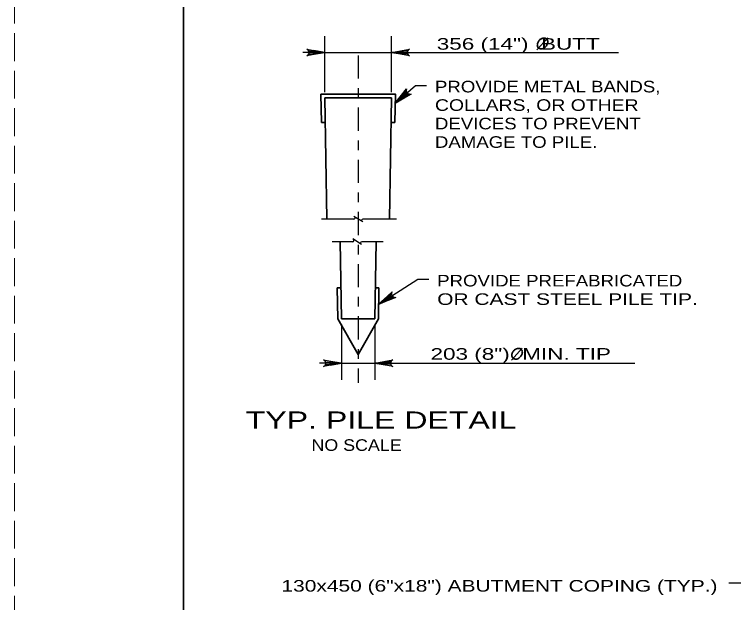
# Model space of a CAD drawing. Extents: x -6.4 to 73.1, y -66 to 0.
# Drawn here: x 0 to 7.44, y -58.43 to -52.34 of the extents above; entities that cross this region are included whole.
import ezdxf
from ezdxf.enums import TextEntityAlignment as Align

# ---------------------------------------------------------------- set-up
doc = ezdxf.new("R2010")
doc.units = 0
doc.header["$LTSCALE"] = 0.048
doc.linetypes.add('DOT_DASHED', pattern=[7.7, 5, -1.2, 0.3, -1.2])
doc.linetypes.add('LONG_DASHED', pattern=[7.5, 6, -1.5])
for name, color, linetype, lineweight in [('1', 7, 'Continuous', 13), ('4', 7, 'Continuous', 25), ('5', 7, 'Continuous', 25), ('63', 7, 'LONG_DASHED', 13)]:
    doc.layers.add(name, color=color, linetype=linetype, lineweight=lineweight)

msp = doc.modelspace()

# ---------------------------------------------------------------- hatches: boundary and pattern name
at = {"layer": '5'}
for points in [[(3.099, -52.71575), (3.099, -52.7535), (3.21242, -52.73458)], [(4.01508, -52.71575), (4.01508, -52.7535), (3.90167, -52.73458)], [(4.03833, -53.20025), (4.01358, -53.17167), (3.94025, -53.26017)], [(3.87675, -55.29392), (3.85625, -55.26217), (3.77117, -55.3395)], [(3.27133, -55.931), (3.27133, -55.96875), (3.38467, -55.94992)], [(3.84275, -55.931), (3.84275, -55.96875), (3.72933, -55.94992)]]:
    msp.add_hatch(color=256, dxfattribs=at).paths.add_polyline_path(points)

# ---------------------------------------------------------------- linework, layer by layer
at = {"layer": '1', "lineweight": 35}
msp.add_lwpolyline([(1.75, -65.25), (33.25, -65.25), (33.25, -44.75), (1.75, -44.75)], close=True, dxfattribs=at)
at = {"layer": '4', "linetype": 'DOT_DASHED'}
msp.add_line((3.557, -52.76425), (3.557, -56.15083), dxfattribs=at)
at = {"layer": '4', "lineweight": 35}
for p, q in [((3.17233, -53.16475), (3.177, -53.46058)), ((3.21242, -53.20417), (3.23217, -54.45908)), ((3.21242, -53.20417), (3.90167, -53.20417)), ((3.90167, -53.20417), (3.88192, -54.45908)), ((3.177, -53.46058), (3.21642, -53.46058)), ((3.89767, -53.46058), (3.93708, -53.46058)), ((3.37208, -54.69267), (3.38467, -55.49142)), ((3.742, -54.69267), (3.72933, -55.49142)), ((3.34142, -55.16983), (3.34533, -55.492)), ((3.34142, -55.16983), (3.38083, -55.16983)), ((3.73325, -55.16983), (3.77258, -55.16983)), ((3.77258, -55.16983), (3.76875, -55.492)), ((3.34533, -55.492), (3.557, -55.85875)), ((3.38467, -55.49142), (3.72933, -55.49142)), ((3.76875, -55.492), (3.557, -55.85875))]:
    msp.add_line(p, q, dxfattribs=at)
at = {"layer": '4'}
for p, q in [((3.51308, -54.45908), (3.17808, -54.45908)), ((3.60533, -54.48808), (3.51292, -54.43)), ((3.95258, -54.45908), (3.60633, -54.45908)), ((3.50067, -54.69267), (3.28917, -54.69267)), ((3.59283, -54.72175), (3.5005, -54.66367)), ((3.81658, -54.69267), (3.59392, -54.69267))]:
    msp.add_line(p, q, dxfattribs=at)
at = {"layer": '4', "lineweight": 35}
msp.add_lwpolyline([(3.17233, -53.16475), (3.94175, -53.16475), (3.93708, -53.46058)], dxfattribs=at)
at = {"layer": '4'}
for centre, start, end in [((3.51185, -54.44546), 275.32859, 57.86724), ((3.60636, -54.47268), 90, 240), ((3.4994, -54.67909), 275.32859, 57.86724), ((3.5939, -54.70631), 90, 240)]:
    msp.add_arc(centre, 0.01364, start, end, dxfattribs=at)
at = {"layer": '5'}
for p, q in [((3.21242, -53.14508), (3.21242, -52.5645)), ((3.90167, -53.14508), (3.90167, -52.5645)), ((3.21242, -52.73458), (2.98558, -52.73458)), ((3.21242, -52.73458), (6.25125, -52.73458)), ((3.90167, -52.73458), (4.1285, -52.73458)), ((3.38467, -55.55042), (3.38467, -56.12)), ((3.72933, -55.55042), (3.72933, -56.12)), ((3.38467, -55.94992), (3.15792, -55.94992)), ((3.38467, -55.94992), (6.42142, -55.94992)), ((3.84275, -55.94992), (3.95617, -55.94992)), ((7.7735, -58.22442), (7.39092, -58.22442))]:
    msp.add_line(p, q, dxfattribs=at)
at = {"layer": '5', "lineweight": 35}
for p, q in [((5.40725, -52.70692), (5.51925, -52.58425)), ((5.14367, -55.91767), (5.25567, -55.79508))]:
    msp.add_line(p, q, dxfattribs=at)
at = {"layer": '5'}
for points in [[(3.21242, -52.73458), (3.026, -52.7695), (3.04033, -52.75958), (3.04775, -52.74708), (3.04992, -52.73458), (3.04775, -52.72208), (3.04033, -52.70958), (3.026, -52.69967), (3.21242, -52.73458), (3.04033, -52.70958), (3.04775, -52.72208), (3.21242, -52.73458), (3.04992, -52.73458), (3.04775, -52.74708), (3.21242, -52.73458), (3.04033, -52.75958)], [(3.90167, -52.73458), (4.08808, -52.69967), (4.07375, -52.70958), (4.06633, -52.72208), (4.06417, -52.73458), (4.06633, -52.74708), (4.07375, -52.75958), (4.08808, -52.7695), (3.90167, -52.73458), (4.07375, -52.75958), (4.06633, -52.74708), (3.90167, -52.73458), (4.06417, -52.73458), (4.06633, -52.72208), (3.90167, -52.73458), (4.07375, -52.70958)], [(3.94025, -53.26017), (4.15083, -53.07783), (4.26425, -53.07783)], [(3.94025, -53.26017), (4.05833, -53.11175), (4.05392, -53.12867), (4.0565, -53.14292), (4.06308, -53.15383), (4.07292, -53.16183), (4.08667, -53.16642), (4.10408, -53.16458), (3.94025, -53.26017), (4.08667, -53.16642), (4.07292, -53.16183), (3.94025, -53.26017), (4.06308, -53.15383), (4.0565, -53.14292), (3.94025, -53.26017), (4.05392, -53.12867)], [(3.77058, -55.33992), (4.17367, -55.08008), (4.28708, -55.08008)], [(3.77058, -55.33992), (3.90833, -55.2095), (3.90167, -55.22567), (3.90217, -55.24017), (3.90717, -55.25183), (3.91575, -55.26125), (3.92875, -55.26775), (3.94617, -55.26833), (3.77058, -55.33992), (3.92875, -55.26775), (3.91575, -55.26125), (3.77058, -55.33992), (3.90717, -55.25183), (3.90217, -55.24017), (3.77058, -55.33992), (3.90167, -55.22567)], [(3.38467, -55.94992), (3.19825, -55.98483), (3.21258, -55.97492), (3.22, -55.96242), (3.22217, -55.94992), (3.22, -55.93742), (3.21258, -55.92492), (3.19825, -55.915), (3.38467, -55.94992), (3.21258, -55.92492), (3.22, -55.93742), (3.38467, -55.94992), (3.22217, -55.94992), (3.22, -55.96242), (3.38467, -55.94992), (3.21258, -55.97492)], [(3.72933, -55.94992), (3.91575, -55.915), (3.90142, -55.92492), (3.894, -55.93742), (3.89183, -55.94992), (3.894, -55.96242), (3.90142, -55.97492), (3.91575, -55.98483), (3.72933, -55.94992), (3.90142, -55.97492), (3.894, -55.96242), (3.72933, -55.94992), (3.89183, -55.94992), (3.894, -55.93742), (3.72933, -55.94992), (3.90142, -55.92492)]]:
    msp.add_lwpolyline(points, dxfattribs=at)
for points in [[(3.099, -52.71575), (3.099, -52.7535), (3.21242, -52.73458)], [(4.01508, -52.71575), (4.01508, -52.7535), (3.90167, -52.73458)], [(4.03833, -53.20025), (4.01358, -53.17167), (3.94025, -53.26017)], [(3.87675, -55.29392), (3.85625, -55.26217), (3.77117, -55.3395)], [(3.27133, -55.931), (3.27133, -55.96875), (3.38467, -55.94992)], [(3.84275, -55.931), (3.84275, -55.96875), (3.72933, -55.94992)]]:
    msp.add_lwpolyline(points, close=True, dxfattribs=at)
at = {"layer": '5', "lineweight": 35}
for points in [[(5.50767, -52.59642), (5.49892, -52.5895), (5.49017, -52.58717), (5.47917, -52.58617), (5.47292, -52.58617), (5.46217, -52.58867), (5.45225, -52.59317), (5.44542, -52.597), (5.43217, -52.60767), (5.42175, -52.62117), (5.4155, -52.63375), (5.41192, -52.64542), (5.41075, -52.65617), (5.41192, -52.66542), (5.41642, -52.6785), (5.42117, -52.68542), (5.43075, -52.69267), (5.44525, -52.69617), (5.46175, -52.69567), (5.48267, -52.68617), (5.49792, -52.673), (5.50942, -52.65717), (5.51692, -52.6405), (5.51942, -52.62217), (5.51617, -52.61025), (5.50817, -52.59642)], [(5.24408, -55.80717), (5.23533, -55.80033), (5.22658, -55.79792), (5.21558, -55.79692), (5.20933, -55.79692), (5.19858, -55.79942), (5.18867, -55.80392), (5.18183, -55.80783), (5.16858, -55.81842), (5.15817, -55.83192), (5.15192, -55.84458), (5.14833, -55.85617), (5.14717, -55.86692), (5.14833, -55.87617), (5.15283, -55.88933), (5.15758, -55.89617), (5.16717, -55.90342), (5.18167, -55.90692), (5.19817, -55.90642), (5.21908, -55.89692), (5.23433, -55.88383), (5.24583, -55.86792), (5.25333, -55.85133), (5.25583, -55.83292), (5.25258, -55.82108), (5.24458, -55.80717)]]:
    msp.add_spline(points, degree=3, dxfattribs=at)
at = {"layer": '63'}
msp.add_lwpolyline([(0, -66), (34, -66), (34, -44), (0, -44)], close=True, dxfattribs=at)

# ---------------------------------------------------------------- texts
at = {"layer": '5'}
for s, height, width, p in [('356 (14")  BUTT', 0.12, 1.45, (5.21342, -52.70583)), ('203 (8")  MIN. TIP', 0.12, 1.45, (5.23904, -55.9135)), ('TYP. PILE DETAIL', 0.1772, 1.4, (3.79479, -56.62592)), ('NO SCALE', 0.12, 1.15, (3.54033, -56.8565))]:
    msp.add_text(s, height=height, dxfattribs=dict(at, width=width)).set_placement(p, align=Align.CENTER)
for s, width, p in [('PROVIDE METAL BANDS,', 1.2, (4.35167, -53.14758)), ('COLLARS, OR OTHER ', 1.25, (4.35167, -53.33883)), ('DEVICES TO PREVENT', 1.2, (4.35167, -53.53)), ('DAMAGE TO PILE.', 1.2, (4.35167, -53.72125)), ('PROVIDE PREFABRICATED', 1.2, (4.37475, -55.15533)), ('OR CAST STEEL PILE TIP.', 1.35, (4.37475, -55.34658))]:
    msp.add_text(s, height=0.12, dxfattribs=dict(at, width=width)).set_placement(p)
at = {"layer": '5', "width": 1.35}
msp.add_text('130x450 (6"x18") ABUTMENT COPING (TYP.)', height=0.12, dxfattribs=at).set_placement((7.27483, -58.31267), align=Align.RIGHT)

doc.saveas('drawing.dxf')
